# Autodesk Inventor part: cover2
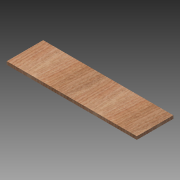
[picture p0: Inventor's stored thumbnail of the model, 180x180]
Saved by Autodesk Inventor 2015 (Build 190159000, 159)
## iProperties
Created: 2015-04
Part Number: cover2
Material: Wood (Birch)
Document SubType Name: Modeling
Designer: sungeun
Density: 0.55 g/cm^3
Appearance: Birch - Natural Polished
Author: sungeun
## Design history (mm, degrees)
sketch "Sketch1" dims "d21" = 0, "d22" = 0
  geometry: L1 (-470, 82)-(-470, 222); L2 (-470, 222)-(-220, 222); L3 (-220, 222)-(-220, 112); L4 (30, 222)-(-220, 222); L5 (30, 82)-(30, 222); L6 (-470, 82)-(30, 82); 4 further points
  constraints: 12 end point, 4 horizontal, 3 vertical, 2 point on line, 1 midpoint, 1 symmetric about line, 8 other
  dimensions: "d2" = 90 deg angle of L2 L1; "d8" = 250 distance of L1.end L2.end; "d23" = 140 distance between parallel lines of L2 L6
extrude "Extrusion1" new body sketch "Sketch1" distance "d6" = 12 (= thickness); taper "d7" = 0 deg
body "Solid1"
other parameters: "thickness" = 12 [user parameter; used in 1 equation term]
